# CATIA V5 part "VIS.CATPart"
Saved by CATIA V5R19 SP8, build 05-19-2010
Part number: VIS
Bounding box of the stored display mesh (mm): x 0 to 70, y -1.5 to 1.5, z -1.5 to 1.5
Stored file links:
  F:\Projet3\VIS.CATPart
  F:\Projet3\Produit1.CATProduct
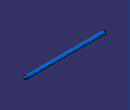
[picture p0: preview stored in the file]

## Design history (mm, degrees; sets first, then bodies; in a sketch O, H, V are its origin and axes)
Parameters
  Longueur = 10 mm
Body1 (main body)
  Sketch1 on yz-plane, origin (0, 0, 0), H (0, 1, 0), V (0, 0, 1)
    circle A1 centre (0, 0) radius 1.5
    radius A1 = 1.5 {= Longueur *0.15}
  Pad1: profile Sketch1, direction (1, 0, 0), length 70 {= Longueur *7}
  Chamfer1: length 1 {= Longueur *0.1}, angle 45, on edge [face of Pad1 from Sketch1.A1 | end face of Pad1]
  Chamfer2: length 1 {= Longueur *0.1}, angle 45, on edge [start face of Pad1 | face of Pad1 from Sketch1.A1]
  Thread1: diameter 3 {= Longueur *0.3}, depth 69, pitch 1 {= Longueur *0.1}, on face of Pad1 from Sketch1.A1, from end face of Pad1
